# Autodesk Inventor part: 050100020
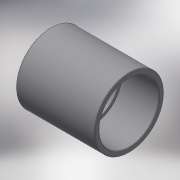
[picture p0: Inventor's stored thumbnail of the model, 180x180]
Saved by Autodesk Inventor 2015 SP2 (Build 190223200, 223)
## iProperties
Created: 2017-10
Part Number: 050100020
Material: Generic
Description: PLASSON SOCKET PVC 20 - CEMENT
Document SubType Name: Modeling
Designer: KIM
Density: 1 g/cm^3
Appearance: Default
Author: KIM
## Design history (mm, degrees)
derived "050100.ipt"
feature "Solid1::050100.ipt"
tag "TaggingFeature1"
body "Solid1"
other parameters: "d0" = 35, "d1" = 25, "d2" = 16, "d3" = 3, "d5" = 18, "d7" = 0.2, "E_" = 25, "H_" = 35, "l_" = 16, "Z_" = 3
